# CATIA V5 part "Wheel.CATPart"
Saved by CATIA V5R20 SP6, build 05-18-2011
Part number: Wheel
Bounding box of the stored display mesh (mm): x -775 to 775, y 0 to 20, z 225 to 1775
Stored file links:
  E:\#01 CATIA Lecture Materials\#06 DMU\#01 DMU KIN Page01 EX01\#01 CATPart\Wheel.CATPart
  E:\#01 CATIA Lecture Materials\#06 DMU\#10 Kinematics Joints\#001 Revolution Joint\FIX.CATPart
  E:\#01 CATIA Lecture Materials\#06 DMU\#10 Kinematics Joints\#001 Revolution Joint\Revolution Joint.CATProduct
  E:\#01 CATIA Lecture Materials\#06 DMU\#10 Kinematics Joints\#001 Revolution Joint\Wheel Part.CATPart
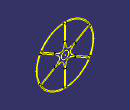
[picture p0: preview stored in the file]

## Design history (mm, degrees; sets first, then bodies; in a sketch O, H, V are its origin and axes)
AxisSystem1: origin (0, 0, 1000), X (1, 0, 0), Y (0, 1, 0), Z (0, 0, 1)
Set1
  DatumCurve1 "Curve.1 ( *CRV105 - wsp *MASTER -  )"
  DatumCurve2 "Curve.2 ( *CRV106 - wsp *MASTER -  )"
  DatumCurve3 "Curve.3 ( *CRV107 - wsp *MASTER -  )"
  DatumCurve4 "Curve.4 ( *CRV108 - wsp *MASTER -  )"
  DatumCurve5 "Curve.22 ( *CRV126 - wsp *MASTER -  )"
  DatumCurve6 "Curve.4 ( *CRV108 - wsp *MASTER -  )"
  DatumCurve7 "Curve.5 ( *CRV109 - wsp *MASTER -  )"
  DatumCurve8 "Curve.6 ( *CRV110 - wsp *MASTER -  )"
  DatumCurve9 "Curve.7 ( *CRV111 - wsp *MASTER -  )"
  DatumCurve10 "Curve.8 ( *CRV112 - wsp *MASTER -  )"
  DatumCurve11 "Curve.9 ( *CRV113 - wsp *MASTER -  )"
  DatumCurve12 "Curve.10 ( *CRV114 - wsp *MASTER -  )"
  DatumCurve13 "Curve.11 ( *CRV115 - wsp *MASTER -  )"
  DatumCurve14 "Curve.12 ( *CRV116 - wsp *MASTER -  )"
  DatumCurve15 "Curve.13 ( *CRV117 - wsp *MASTER -  )"
  DatumCurve16 "Curve.14 ( *CRV118 - wsp *MASTER -  )"
  DatumCurve17 "Curve.15 ( *CRV119 - wsp *MASTER -  )"
  DatumCurve18 "Curve.16 ( *CRV120 - wsp *MASTER -  )"
  DatumCurve19 "Curve.17 ( *CRV121 - wsp *MASTER -  )"
  DatumCurve20 "Curve.18 ( *CRV122 - wsp *MASTER -  )"
  DatumCurve21 "Curve.19 ( *CRV123 - wsp *MASTER -  )"
  DatumCurve22 "Curve.20 ( *CRV124 - wsp *MASTER -  )"
  DatumCurve23 "Curve.21 ( *CRV125 - wsp *MASTER -  )"
  DatumCurve24 "Curve.22 ( *CRV126 - wsp *MASTER -  )"
  DatumCurve25 "Curve.23 ( *CRV127 - wsp *MASTER -  )"
  DatumCurve26 "Curve.24 ( *CRV128 - wsp *MASTER -  )"
  DatumCurve27 "Curve.25 ( *CRV129 - wsp *MASTER -  )"
  DatumCurve28 "Curve.26 ( *CRV130 - wsp *MASTER -  )"
  DatumCurve29 "Curve.27 ( *CRV131 - wsp *MASTER -  )"
  DatumCurve30 "Curve.28 ( *CRV132 - wsp *MASTER -  )"
  DatumCurve31 "Curve.29 ( *CRV133 - wsp *MASTER -  )"
  DatumCurve32 "Curve.30 ( *CRV134 - wsp *MASTER -  )"
  DatumCurve33 "Curve.31 ( *CRV135 - wsp *MASTER -  )"
  DatumCurve34 "Curve.32 ( *CRV136 - wsp *MASTER -  )"
  DatumCurve35 "Curve.33 ( *CRV137 - wsp *MASTER -  )"
  DatumCurve36 "Curve.34 ( *CRV138 - wsp *MASTER -  )"
  DatumCurve37 "Curve.35 ( *CRV139 - wsp *MASTER -  )"
  DatumCurve38 "Curve.36 ( *CRV140 - wsp *MASTER -  )"
  DatumCurve39 "Curve.37 ( *CRV141 - wsp *MASTER -  )"
  DatumCurve40 "Curve.38 ( *CRV142 - wsp *MASTER -  )"
  Point1 "Point.1 ( PT1 - wsp *MASTER -  )": stored without definition
  Point2 "Point.2 ( PT2 - wsp *MASTER -  )": stored without definition
  Point3 "Point.3 ( PT3 - wsp *MASTER -  )": stored without definition
  Point4 "Point.4 ( PT4 - wsp *MASTER -  )": stored without definition
  Point5 "Point.5 ( PT5 - wsp *MASTER -  )": stored without definition
  Point6 "Point.6 ( PT6 - wsp *MASTER -  )": stored without definition
  Point7 "Point.7 ( PTM - wsp *MASTER -  )": stored without definition
  DatumCurve41 to DatumCurve46
  Line1 to Line7: stored without definition
Body1 (main body)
